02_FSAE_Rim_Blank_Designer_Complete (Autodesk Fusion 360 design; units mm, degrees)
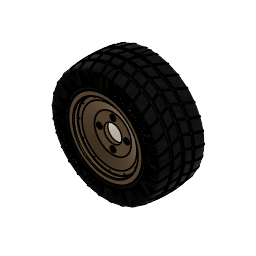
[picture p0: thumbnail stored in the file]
part number: 2026-07-27-09-56-27-671
sketch "Sketch1" plane through (0, 0, 0) normal (1, 0, 0) x axis (0, 1, 0)
  line L1 (153.5, 0) -> (0, 0)
  line L2 (0, 119.5) -> (0, 104)
  line L3 (143.5, 124.5) -> (5, 124.5)
  line L4 (148.5, 134.75) -> (148.5, 129.5)
  line L5 (153.5, 138.25) -> (152, 138.25)
  line L6 (2.5, 119.5) -> (2.5, 104)
  line L7 (143.5, 122) -> (5, 122)
  line L8 (151, 134.75) -> (151, 129.5)
  line L9 (153.5, 135.75) -> (152, 135.75)
  line L10 (2.5, 104) -> (0, 104)
  line L11 (153.5, 135.75) -> (153.5, 138.25)
  arc A1 centre (152, 134.75) radius 3.5 clockwise from (148.5, 134.75) to (152, 138.25)
  arc A2 centre (143.5, 129.5) radius 5 clockwise from (148.5, 129.5) to (143.5, 124.5)
  arc A3 centre (5, 119.5) radius 5 clockwise from (0, 119.5) to (5, 124.5)
  arc A4 centre (5, 119.5) radius 2.5 clockwise from (2.5, 119.5) to (5, 122)
  arc A5 centre (143.5, 129.5) radius 7.5 clockwise from (151, 129.5) to (143.5, 122)
  arc A6 centre (152, 134.75) radius 1 clockwise from (151, 134.75) to (152, 135.75)
  point P1 (0, 0)
  point P2 (0, 0)
  point P4 (0, 104)
  point P3 (153.5, 0)
  point P7 (153.5, 138.25)
  point P6 (148.5, 124.5)
  point P5 (0, 124.5)
  coincident P1 P2
  horizontal L1
  perpendicular L1 L2
  perpendicular L2 L3
  perpendicular L3 L4
  perpendicular L4 L5
  vertical P1 P4
  vertical P3 P7
  tangent L4 A1
  tangent L5 A1
  coincident P6 L3
  coincident P6 L4
  tangent L3 A2
  tangent L4 A2
  coincident P5 L2
  coincident P5 L3
  tangent L2 A3
  tangent L3 A3
  equal A2 A3
  perpendicular L6 L10
  perpendicular L9 L11
  dimension "d1" distance P2 P3 = 153.5
  dimension "d2" = 208
  dimension "d3" = 249
  dimension "d4" = 276.5
  dimension "d5" distance P5 P6 = 148.5
  dimension "d6" radius A1 = 3.5
  dimension "d7" radius A2 = 5
  dimension "d8" = 2.5
revolve "Revolve1" sketch "Sketch1" AlongAngle 360 bodies "FSAE Rim Back"
sketch "Sketch2" plane through (0, 0, 0) normal (0, -1, 0) x axis (1, 0, 0)
  circle C1 centre (0, 0) radius 104
  circle C2 centre (0, 0) radius 119.5
  circle C3 centre (0, 0) radius 112
  circle C4 centre (0, 112) radius 2.15
  point P1 (0, 0)
  point P3 (0, 0)
  point P4 (0, 112)
  coincident P1 P3
  coincident C3 P4
  vertical P3 P4
  dimension "d10" diameter C3 = 224
  dimension "d11" diameter C4 = 4.3
extrude "Extrude1" cut sketch "Sketch2" profile of C4 to an object
circular_pattern "C-Pattern1" TotalAngle 360
canvas "Canvas1"
move "Move1"
sketch "Sketch4" plane through (0, 0, 0) normal (1, 0, 0) x axis (0, 1, 0)
  line L1 (14, 0) -> (0, 0)
  line L2 (14, 72.5) -> (14, 0)
  line L3 (-8, 102.5) -> (14, 72.5)
  line L4 (-8, 124.5) -> (-8, 102.5)
  line L5 (-23.5, 124.5) -> (-8, 124.5)
  line L6 (-23.5, 138) -> (-23.5, 124.5)
  line L7 (-28.25, 138) -> (-23.5, 138)
  line L8 (-28.25, 0) -> (-28.25, 138)
  line L9 (0, 0) -> (-28.25, 0)
  line L10 (-13, 118.1658) -> (-28.25, 119.5)
  line L11 (-13, 102.5) -> (-13, 118.1658)
  line L12 (0, 68.6338) -> (-13, 102.5)
  line L13 (0, 0) -> (0, 68.6338)
  point P1 (0, 0)
  point P2 (0, 0)
  point P11 (0, 0)
  point P12 (-28.25, 119.5)
  point P5 (-8, 102.5)
  point P14 (-13, 102.5)
  point P3 (14, 0)
  point P4 (14, 72.5)
  point P6 (-8, 124.5)
  point P8 (-23.5, 138)
  point P9 (-28.25, 138)
  coincident P1 P2
  horizontal L1
  perpendicular L1 L2
  perpendicular L1 L4
  perpendicular L4 L5
  perpendicular L5 L6
  perpendicular L6 L7
  coincident P1 P11
  collinear L1 L9
  perpendicular L8 L9
  coincident L8 P12
  parallel L8 L11
  vertical L13
  horizontal P5 P14
  dimension "d29" distance P2 P3 = 14
  dimension "d30" = 145
  dimension "d31" = 205
  dimension "d32" = 249
  dimension "d33" = 276
  dimension "d34" distance P4 P6 = 22
  dimension "d35" distance P6 P8 = 15.5
  dimension "d36" distance P8 P9 = 4.75
  dimension "d37" distance L4 L11 = 5
  dimension "d38" angle L12 L13 = 159
  dimension "d39" angle L10 L11 = 95
  dimension "d40" = 239
revolve "Revolve3" sketch "Sketch4" AlongAngle 360 bodies "FSAE Rim Front"
sketch "Sketch5" plane through (0, 0, 0) normal (0, -1, 0) x axis (1, 0, 0)
  circle C1 centre (0, 0) radius 68.6338
  circle C2 centre (0, 0) radius 33
  point P1 (0, 0)
  point P3 (0, 0)
  coincident P1 P3
  dimension "d42" diameter C2 = 66
extrude "Extrude2" cut sketch "Sketch5" profile of C2 to an object
sketch "Sketch6" plane through (0, 0, 0) normal (0, -1, 0) x axis (1, 0, 0)
  circle C1 centre (0, 0) radius 33
  circle C2 centre (0, 0) radius 68.6338
  circle C3 centre (0, 0) radius 50.8
  point P1 (0, 0)
  point P4 (0, 0)
  point P3 (0, 50.8)
  coincident P1 P4
  coincident P3 C3
  vertical P1 P3
  dimension "d45" diameter C3 = 101.6
hole "Hole1" HoleDiameter 10.5 TipAngle 180 CBDepth 5 CBDiameter 20
chamfer "Chamfer2" sketch "Sketch1" distance 0.5
circular_pattern "C-Pattern2" TotalAngle 360
sketch "Sketch7" plane through (0, -13, 0) normal (0, -1, 0) x axis (1, 0, 0)
  circle C1 centre (0, 0) radius 102.5
  circle C2 centre (0, 0) radius 118.1658
  circle C3 centre (0, 0) radius 112
  point P1 (0, 0)
  point P3 (0, 0)
  point P4 (0, 112)
  coincident P1 P3
  coincident C3 P4
  vertical P1 P4
  dimension "d53" diameter C3 = 224
hole "Hole2" HoleDiameter 4.3 TipAngle 180
circular_pattern "C-Pattern3" TotalAngle 360
fillet "Fillet1" radius 1 3 2
chamfer "Chamfer1" distance 0.5
form "Form1" bodies "Tire"
fillet "Fillet2" radius 5
sketch "Sketch8" plane through (0, 0, 0) normal (1, 0, 0) x axis (0, 1, 0)
  line L1 (47.5, 224.911) -> (47.5, 204.911)
  line L2 (57.5, 224.911) -> (47.5, 224.911)
  line L3 (57.5, 204.9943) -> (57.5, 224.911)
  line L4 (87.5, 224.911) -> (87.5, 204.2438)
  line L5 (97.5, 224.911) -> (87.5, 224.911)
  line L6 (97.5, 203.6595) -> (97.5, 224.911)
  line L7 (17.5, 224.911) -> (17.5, 203.6595)
  line L8 (7.5, 224.911) -> (17.5, 224.911)
  line L9 (7.5, 202.9073) -> (7.5, 224.911)
  arc A1 centre (57.5, -395.0057) radius 600 clockwise from (-46, 196) to (161, 196)
  point P2 (-46, 196)
  point P3 (161, 196)
  point P8 (57.5, 204.9943)
  point P9 (87.5, 204.2438)
  point P12 (97.5, 203.6595)
  point P13 (17.5, 203.6595)
  point P16 (7.5, 202.9073)
  point P5 (47.5, 204.911)
  point P1 (0, 0)
  point P6 (47.5, 224.911)
  point P7 (57.5, 224.911)
  horizontal P2 P3
  vertical L1
  perpendicular L1 L2
  midpoint A1 P8
  perpendicular L2 L3
  coincident A1 P9
  parallel L3 L4
  perpendicular L4 L5
  coincident A1 P12
  perpendicular L5 L6
  coincident A1 P13
  perpendicular L5 L7
  perpendicular L7 L8
  coincident A1 P16
  perpendicular L8 L9
  collinear L2 L8
  collinear L2 L5
  equal L2 L8
  equal L2 L5
  coincident A1 P5
  dimension "d68" radius A1 = 600
  dimension "d69" distance P1 P3 = 196
  dimension "d70" distance P1 P2 = 46
  dimension "d71" distance P1 P3 = 161
  dimension "d73" distance P6 P7 = 10
  dimension "d74" distance L1 L7 = 30
  dimension "d75" distance L3 L4 = 30
  dimension "d76" distance P5 P6 = 20
revolve "Revolve4" AlongAngle 360
revolve "Revolve5" sketch "Sketch8" AlongAngle 360
work_plane "WorkPlane1" AlongDistance 275 ExtraOffset 0
sketch "Sketch9" plane through (0, 0, 275) normal (0, 0, 1) x axis (1, 0, 0)
  line L1 (-48.7008, 53.5011) -> (0, -75.7953)
  line L2 (0, 197.5142) -> (-48.7008, 53.5011)
  line L3 (-43.392, 53.5917) -> (4.6791, -74.0329)
  line L4 (4.7365, 195.9124) -> (-43.392, 53.5917)
  line L5 (4.6791, -74.0329) -> (0, -75.7953)
  line L6 (0, 197.5142) -> (4.7365, 195.9124)
  perpendicular L3 L5
  perpendicular L2 L6
  dimension "d80" = 5
step "SurfaceExtend" extendDistance 125
extrude "Extrude3" cut sketch "Sketch9" to an object
circular_pattern "C-Pattern4" countU 30 TotalAngle 360
remove_body "RemoveBody1"
remove_body "RemoveBody2"
work_plane "WorkPlane2" AlongDistance -150 ExtraOffset 0
sketch "Sketch10" plane through (0, -150, 0) normal (0, 1, 0) x axis (1, 0, 0)
  circle C1 centre (0, 0) radius 157.5
  point P1 (0, 0)
  point P2 (0, 0)
  coincident P1 P2
  dimension "d88" diameter C1 = 315
  dimension "d89" Text1-Height = 20
extrude "Extrude4" sketch "Sketch10" blind 2
circular_pattern "C-Pattern5" TotalAngle 360
named bodies: "FSAE Rim Back", "FSAE Rim Front", "Tire"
